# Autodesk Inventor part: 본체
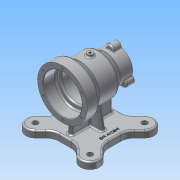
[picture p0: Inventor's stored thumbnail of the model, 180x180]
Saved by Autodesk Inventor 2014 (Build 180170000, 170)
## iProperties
Created: 2017-03
Part Number: 본체
Material: 알루미늄 6061
Document SubType Name: Modeling
Designer: NET
Density: 2.71 g/cm^3
Appearance: 알루미늄 - 평지
Mass: 1008.06 g
Surface Area: 842.102 cm^2
Volume: 371.977 cm^3
Author: NET
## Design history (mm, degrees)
sketch "스케치1"
  geometry: L1 (-50, 0)-(-50, 45); L2 (-50, 45)-(-30, 45); L3 (-30, 45)-(-19, 36); L4 (-19, 36)-(15, 36); L5 (50, 27.5)-(50, 0); L6 (50, 0)-(-50, 0); L7 (27, 27.5)-(50, 27.5); L8 (27, 27.5)-(15, 36); 2 further points
  constraints: 16 end point, 4 parallel, 1 coincident, 1 midpoint, 1 perpendicular, 1 vertical
  dimensions: "d0" = 90 diameter of L2 L6; "d1" = 20 distance from line of L1 L2.end; "d2" = 31 distance from line of L1 L3.end; "d3" = 65 distance from line of L1 L4.end; "d4" = 100 distance between parallel lines of L5 L1; "d6" = 72 diameter of L4 L6; "d7" = 55 diameter of L7 L6; "d8" = 23 distance from line of L5 L7.start
revolve "회전1" sketch "스케치1" stored, may be unused: angle "d9" = 90 deg
sketch "스케치2"
  geometry: L1 (-50, 35)-(-30, 35); L2 (-27, 32)-(-27, 29); L3 (-24, 26)-(17, 26); L4 (20, 23)-(20, 20.5); L5 (23, 17.5)-(50, 17.5); L6 (50, 17.5)-(50, 0); L7 (50, 0)-(-50, 0); L8 (-50, 0)-(-50, 35); L9 (-50, -45)-(-50, 45) reference; A1 r 3 centre (-30, 32) between (-27, 32) and (-30, 35); A2 r 3 centre (-24, 29) between (-27, 29) and (-24, 26); A3 r 3 centre (17, 23) between (20, 23) and (17, 26); A4 r 3 centre (23, 20.5) between (20, 20.5) and (23, 17.5); 5 further points
  constraints: 16 end point, 8 point on circle, 8 point on line, 8 tangent, 5 parallel, 4 centre point, 3 equal radius, 1 horizontal, 1 horizontal alignment, 1 midpoint, 1 perpendicular, 1 vertical
  dimensions: "d10" = 23 distance between parallel lines of L2 L8; "d11" = 30 distance between parallel lines of L6 L4; "d12" = 47 distance of point (-27, 26) point (20, 26); "d13" = 70 diameter of L1 L7; "d14" = 52 diameter of L3 L7; "d15" = 35 diameter of L5 L7; "d17" = 3 radius of A1
revolve "회전2" sketch "스케치2" stored, may be unused: angle "d16" = 90 deg
fillet "모깎기1" dims "d18" = 3
sketch "스케치3"
  geometry: C1 r 17.5 at (0, 0) reference
sketch "스케치4"
  geometry: L1 (0, -27.5)-(0, -16.662); L2 (7, -27.5)-(7, -16.662); L3 (-7, -16.662)-(-7, -27.5); C1 r 17.5 at (0, 0) reference; A1 r 7 centre (0, -27.5) between (-7, -27.5) and (7, -27.5); A2 r 7 centre (0, -16.662) between (7, -16.662) and (-7, -16.662); 2 further points
  constraints: 8 end point, 4 point on circle, 4 tangent, 2 centre point, 2 vertical alignment, 1 midpoint, 1 parallel, 1 vertical, 1 other
  dimensions: "d19" = 7 radius of A1
extrude "돌출1" join sketch "스케치4" distance "d20" = 15; taper "d21" = 0 deg
extrude "돌출2" cut sketch "스케치3" distance "d25" = 15; taper "d26" = 0 deg
fillet "모깎기2" dims "d27" = 3
fillet "모깎기3" dims "d28" = 1
hole "구멍1" diameter "d31" = 3.242; stored, may be unused: countersink angle "d35" = 90 deg, drill point angle "d37" = 118 deg; dims "d29" = 10, "d30" = 10, "d32" = 9, "d33" = 4, "d34" = 2, "d36" = 11
sketch "스케치6"
  geometry: C1 r 35 at (0, 0) reference; 1 further point
  constraints: 1 vertical alignment
  dimensions: "d41" = 40 distance of point (0, 40) C1.centre
hole "구멍2" sketch "스케치6" at (0, 40) diameter "d42" = 3.242; stored, may be unused: countersink angle "d46" = 90 deg, drill point angle "d48" = 118 deg; dims "d43" = 9, "d44" = 4, "d45" = 2, "d47" = 11
node "작업 평면1"
sketch "스케치7"
  geometry: L1 (45, -45)-(-45, -45); L2 (-45, -45)-(-45, 45); L3 (-45, 45)-(45, 45); L4 (45, 45)-(45, -45); L5 (45, -45)-(-45, 45); L6 (-45, -45)-(45, 45); L7 (6.944, 6.944)-(49.497, 49.497); L8 (18.965, -5.077)-(61.518, 37.477); L9 (37.477, 61.518)-(-5.077, 18.965); A1 r 17 centre (6.944, 6.944) between (-5.077, 18.965) and (18.965, -5.077); A2 r 17 centre (49.497, 49.497) between (61.518, 37.477) and (37.477, 61.518); 2 further points
  constraints: 20 end point, 4 point on circle, 4 tangent, 3 midpoint, 3 parallel, 2 centre point, 2 point on line, 1 horizontal, 1 perpendicular
  dimensions: "d53" = 90 distance between parallel lines of L1 L3; "d54" = 90 distance between parallel lines of L4 L2; "d55" = 70 distance of point (0, 0) L7.end; "d56" = 34 distance between parallel lines of L8 L9
extrude "돌출3" join sketch "스케치7" distance "d57" = 12; taper "d58" = 0 deg
extrude "돌출4" join sketch "스케치7" distance "d59" = 12; taper "d60" = 0 deg
fillet "모깎기4" dims "d64" = 25
hole "구멍3" diameter "d67" = 10; stored, may be unused: countersink angle "d71" = 90 deg, drill point angle "d73" = 118 deg; dims "d65" = 10, "d66" = 10, "d68" = 9, "d69" = 4, "d70" = 2, "d72" = 11
sketch "스케치8"
  geometry: L1 (4, -37)-(-4, -37); L2 (-4, -37)-(-4, 37); L3 (-4, 37)-(4, 37); L4 (4, 37)-(4, -37); L5 (4, -37)-(-4, 37); L6 (-4, -37)-(4, 37); L7 (25, -4)-(-25, -4); L8 (-25, -4)-(-25, 4); L9 (-25, 4)-(25, 4); L10 (25, 4)-(25, -4); L11 (25, -4)-(-25, 4); L12 (-25, -4)-(25, 4); 1 further point
  constraints: 24 end point, 4 midpoint, 4 parallel, 2 horizontal, 2 perpendicular
  dimensions: "d77" = 37 distance from line of point (0, 0) L1; "d78" = 37 distance from line of L3 point (0, 0) (derived); "d79" = 8 distance between parallel lines of L4 L2; "d80" = 25 distance from line of point (0, 0) L8; "d81" = 8 distance between parallel lines of L7 L9; "d109" = 25 distance from line of L10 point (0, 0) (derived)
extrude "돌출5" join sketch "스케치8" stored distance "d82" = 12; taper "d83" = 0 deg
feature "면 기울기1" dims angle "d84" = 10 deg
fillet "모깎기5" dims "d85" = 3
fillet "모깎기6" dims "d86" = 3
fillet "모깎기7" dims "d87" = 3
node "작업 평면2"
sketch "스케치9"
  geometry: L1 (45, -50)-(-45, -50) reference; C1 r 5 at (0, 0); 1 further point
  constraints: 1 centre point, 1 coincident
  dimensions: "d89" = 10 diameter of C1; "d90" = 50 distance from line of L1 C1.centre
extrude "돌출6" join sketch "스케치9" stored distance "d91" = 12; taper "d92" = 0 deg
fillet "모깎기8" dims "d93" = 3
hole "구멍4" diameter "d96" = 4.134; stored, may be unused: countersink angle "d100" = 90 deg, drill point angle "d102" = 118 deg; dims "d94" = 10, "d95" = 10, "d97" = 30, "d98" = 4, "d99" = 2, "d101" = 30
sketch "스케치10"
  geometry: 2 further points
  constraints: 1 horizontal alignment, 1 other
  dimensions: "d103" = 35 distance of point (35, 0) point (0, 0)
feature "엠보싱1" sketch "스케치10" dims "d0" = 90, "d1" = 20, "d2" = 31, "d3" = 65, "d4" = 100, "d6" = 72, "d7" = 55, "d8" = 23, "d104" = 0.5, "d105" = 0
chamfer "모따기1" distance "d106" = 1; stored, may be unused: second distance "d107" = 2, angle "d108" = 45 deg
node "솔리드1"
pattern_circular "원형 패턴1" dims angle "d23" = 360 deg
pattern_circular "원형 패턴2" dims angle "d39" = 360 deg
pattern_circular "원형 패턴3" dims angle "d50" = 360 deg
pattern_circular "원형 패턴4" dims angle "d62" = 360 deg
pattern_circular "원형 패턴5" dims angle "d75" = 360 deg
other parameters: "d52" = -82
